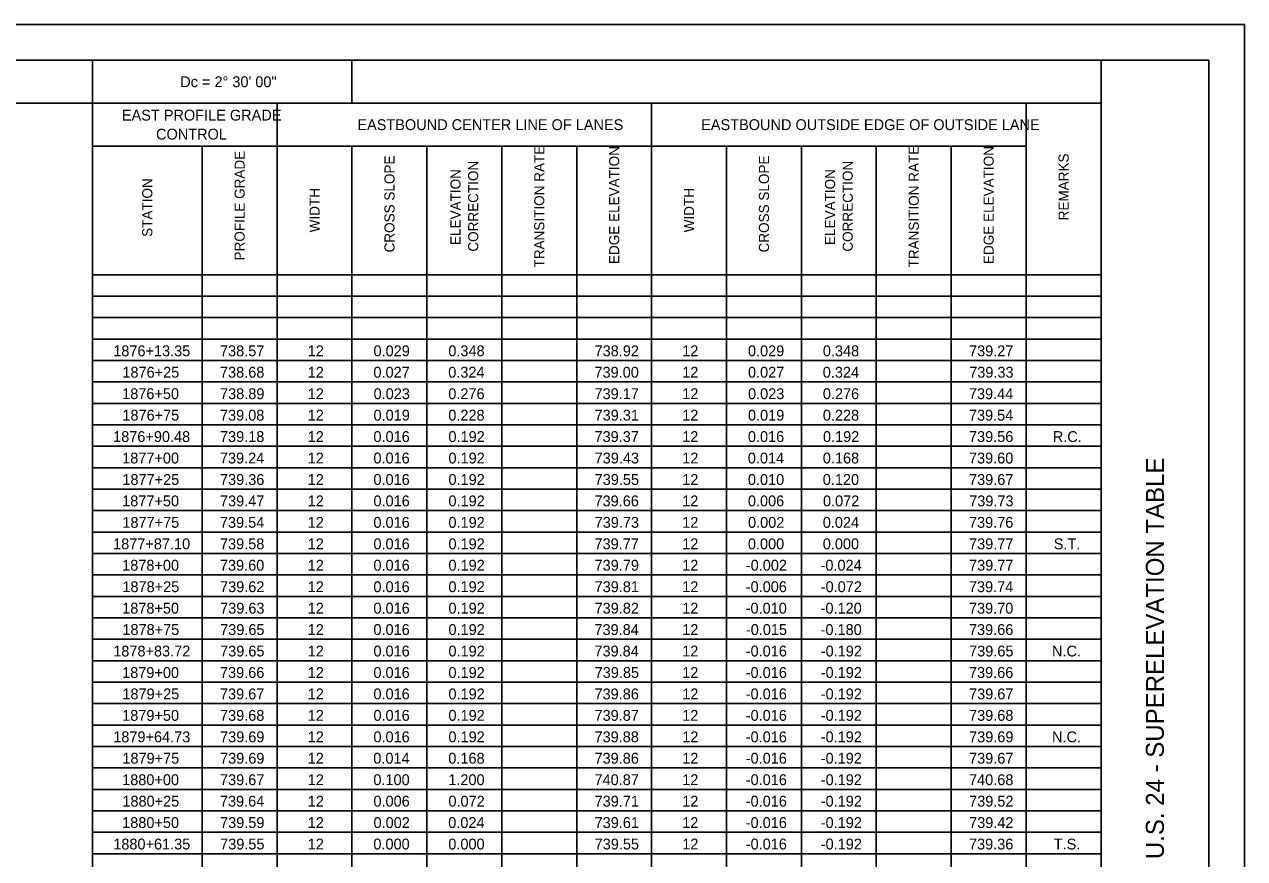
# Model space of a CAD drawing. Extents: x -174 to 34, y 0 to 22.
# Drawn here: x 17 to 34, y 10.38 to 22 of the extents above; entities that cross this region are included whole.
import ezdxf

# ---------------------------------------------------------------- set-up
doc = ezdxf.new("R2010")
doc.units = 0
for name, color, linetype in [('Default', 7, 'Continuous'), ('SH_Border', 7, 'Continuous'), ('SH_Cut_Line', 7, 'Continuous'), ('SH_Data', 7, 'Continuous')]:
    doc.layers.add(name, color=color, linetype=linetype)

msp = doc.modelspace()

# ---------------------------------------------------------------- linework, layer by layer
at = {"layer": 'Default'}
for p, q in [((1.5, 21.5), (32, 21.5)), ((17.947, 21.5), (17.947, 2.37)), ((21.564, 21.5), (21.564, 20.903)), ((32, 21.5), (32, 2.37)), ((1.5, 20.903), (32, 20.903)), ((20.521, 20.903), (20.521, 18.513)), ((25.739, 20.903), (25.739, 18.513)), ((30.956, 20.903), (30.956, 18.513)), ((17.947, 20.305), (30.956, 20.305)), ((19.477, 20.305), (19.477, 18.513)), ((21.564, 20.305), (21.564, 18.513)), ((22.608, 20.305), (22.608, 18.513)), ((23.651, 20.305), (23.651, 18.513)), ((24.695, 20.305), (24.695, 18.513)), ((26.782, 20.305), (26.782, 18.513)), ((27.826, 20.305), (27.826, 18.513)), ((28.869, 20.305), (28.869, 18.513)), ((29.913, 20.305), (29.913, 18.513)), ((17.947, 18.513), (32, 18.513)), ((19.477, 18.513), (19.477, 2.37)), ((20.521, 18.513), (20.521, 2.37)), ((21.564, 18.513), (21.564, 2.37)), ((22.608, 18.513), (22.608, 2.37)), ((23.651, 18.513), (23.651, 2.37)), ((24.695, 18.513), (24.695, 2.37)), ((25.739, 18.513), (25.739, 2.37)), ((26.782, 18.513), (26.782, 2.37)), ((27.826, 18.513), (27.826, 2.37)), ((28.869, 18.513), (28.869, 2.37)), ((29.913, 18.513), (29.913, 2.37)), ((30.956, 18.513), (30.956, 2.37)), ((17.947, 18.215), (32, 18.215)), ((17.947, 17.916), (32, 17.916)), ((17.947, 17.617), (32, 17.617)), ((17.947, 17.319), (32, 17.319)), ((17.947, 17.02), (32, 17.02)), ((17.947, 16.721), (32, 16.721)), ((17.947, 16.423), (32, 16.423)), ((17.947, 16.124), (32, 16.124)), ((17.947, 15.825), (32, 15.825)), ((17.947, 15.527), (32, 15.527)), ((17.947, 15.228), (32, 15.228)), ((17.947, 14.929), (32, 14.929)), ((17.947, 14.631), (32, 14.631)), ((17.947, 14.332), (32, 14.332)), ((17.947, 14.033), (32, 14.033)), ((17.947, 13.735), (32, 13.735)), ((17.947, 13.436), (32, 13.436)), ((17.947, 13.137), (32, 13.137)), ((17.947, 12.839), (32, 12.839)), ((17.947, 12.54), (32, 12.54)), ((17.947, 12.241), (32, 12.241)), ((17.947, 11.943), (32, 11.943)), ((17.947, 11.644), (32, 11.644)), ((17.947, 11.345), (32, 11.345)), ((17.947, 11.047), (32, 11.047)), ((17.947, 10.748), (32, 10.748)), ((17.947, 10.449), (32, 10.449))]:
    msp.add_line(p, q, dxfattribs=at)
at = {"layer": 'SH_Border'}
msp.add_line((32, 0.5), (32, 21.5), dxfattribs=at)
msp.add_lwpolyline([(1.5, 21.5), (33.5, 21.5), (33.5, 0.5), (1.5, 0.5)], close=True, dxfattribs=at)
at = {"layer": 'SH_Cut_Line'}
msp.add_lwpolyline([(0, 0), (34, 0), (34, 22), (0, 22)], close=True, dxfattribs=at)

# ---------------------------------------------------------------- texts
at = {"layer": 'Default'}
for s, height, p in [('Dc = 2° 30\' 00"', 0.15112, (19.171, 21.126)), ('EAST PROFILE GRADE ', 0.15112, (18.358, 20.661)), ('EASTBOUND CENTER LINE OF LANES', 0.15112, (21.639, 20.528)), ('EASTBOUND OUTSIDE EDGE OF OUTSIDE LANE', 0.15112, (26.429, 20.528)), ('CONTROL', 0.1511, (18.834, 20.396)), ('1876+13.35', 0.1511, (18.238, 17.378)), ('738.57', 0.1511, (19.725, 17.378)), ('12', 0.1511, (20.947, 17.378)), ('0.029', 0.1511, (21.864, 17.378)), ('0.348', 0.1511, (22.906, 17.378)), ('738.92', 0.1511, (24.944, 17.378)), ('12', 0.1511, (26.165, 17.378)), ('0.029', 0.1511, (27.081, 17.378)), ('0.348', 0.1511, (28.124, 17.378)), ('739.27', 0.1511, (30.161, 17.378)), ('1876+25', 0.1511, (18.365, 17.08)), ('738.68', 0.1511, (19.725, 17.08)), ('12', 0.1511, (20.947, 17.08)), ('0.027', 0.1511, (21.863, 17.08)), ('0.324', 0.1511, (22.905, 17.08)), ('739.00', 0.1511, (24.942, 17.08)), ('12', 0.1511, (26.165, 17.08)), ('0.027', 0.1511, (27.081, 17.08)), ('0.324', 0.1511, (28.123, 17.08)), ('739.33', 0.1511, (30.163, 17.08)), ('1876+50', 0.1511, (18.362, 16.781)), ('738.89', 0.1511, (19.726, 16.781)), ('12', 0.1511, (20.947, 16.781)), ('0.023', 0.1511, (21.865, 16.781)), ('0.276', 0.1511, (22.906, 16.781)), ('739.17', 0.1511, (24.943, 16.781)), ('12', 0.1511, (26.165, 16.781)), ('0.023', 0.1511, (27.082, 16.781)), ('0.276', 0.1511, (28.124, 16.781)), ('739.44', 0.1511, (30.159, 16.781)), ('1876+75', 0.1511, (18.365, 16.482)), ('739.08', 0.1511, (19.725, 16.482)), ('12', 0.1511, (20.947, 16.482)), ('0.019', 0.1511, (21.864, 16.482)), ('0.228', 0.1511, (22.906, 16.482)), ('739.31', 0.1511, (24.944, 16.482)), ('12', 0.1511, (26.165, 16.482)), ('0.019', 0.1511, (27.081, 16.482)), ('0.228', 0.1511, (28.124, 16.482)), ('739.54', 0.1511, (30.159, 16.482)), ('1876+90.48', 0.1511, (18.236, 16.184)), ('739.18', 0.1511, (19.725, 16.184)), ('12', 0.1511, (20.947, 16.184)), ('0.016', 0.1511, (21.863, 16.184)), ('0.192', 0.1511, (22.908, 16.184)), ('739.37', 0.1511, (24.943, 16.184)), ('12', 0.1511, (26.165, 16.184)), ('0.016', 0.1511, (27.08, 16.184)), ('0.192', 0.1511, (28.126, 16.184)), ('739.56', 0.1511, (30.16, 16.184)), ('R.C.', 0.1511, (31.328, 16.184)), ('1877+00', 0.1511, (18.362, 15.885)), ('739.24', 0.1511, (19.724, 15.885)), ('12', 0.1511, (20.947, 15.885)), ('0.016', 0.1511, (21.863, 15.885)), ('0.192', 0.1511, (22.908, 15.885)), ('739.43', 0.1511, (24.945, 15.885)), ('12', 0.1511, (26.165, 15.885)), ('0.014', 0.1511, (27.079, 15.885)), ('0.168', 0.1511, (28.124, 15.885)), ('739.60', 0.1511, (30.16, 15.885)), ('1877+25', 0.1511, (18.365, 15.586)), ('739.36', 0.1511, (19.725, 15.586)), ('12', 0.1511, (20.947, 15.586)), ('0.016', 0.1511, (21.863, 15.586)), ('0.192', 0.1511, (22.908, 15.586)), ('739.55', 0.1511, (24.945, 15.586)), ('12', 0.1511, (26.165, 15.586)), ('0.010', 0.1511, (27.08, 15.586)), ('0.120', 0.1511, (28.123, 15.586)), ('739.67', 0.1511, (30.161, 15.586)), ('1877+50', 0.1511, (18.362, 15.288)), ('739.47', 0.1511, (19.725, 15.288)), ('12', 0.1511, (20.947, 15.288)), ('0.016', 0.1511, (21.863, 15.288)), ('0.192', 0.1511, (22.908, 15.288)), ('739.66', 0.1511, (24.943, 15.288)), ('12', 0.1511, (26.165, 15.288)), ('0.006', 0.1511, (27.08, 15.288)), ('0.072', 0.1511, (28.126, 15.288)), ('739.73', 0.1511, (30.163, 15.288)), ('1877+75', 0.1511, (18.365, 14.989)), ('739.54', 0.1511, (19.724, 14.989)), ('12', 0.1511, (20.947, 14.989)), ('0.016', 0.1511, (21.863, 14.989)), ('0.192', 0.1511, (22.908, 14.989)), ('739.73', 0.1511, (24.945, 14.989)), ('12', 0.1511, (26.165, 14.989)), ('0.002', 0.1511, (27.082, 14.989)), ('0.024', 0.1511, (28.123, 14.989)), ('739.76', 0.1511, (30.16, 14.989)), ('1877+87.10', 0.1511, (18.236, 14.69)), ('739.58', 0.1511, (19.725, 14.69)), ('12', 0.1511, (20.947, 14.69)), ('0.016', 0.1511, (21.863, 14.69)), ('0.192', 0.1511, (22.908, 14.69)), ('739.77', 0.1511, (24.943, 14.69)), ('12', 0.1511, (26.165, 14.69)), ('0.000', 0.1511, (27.08, 14.69)), ('0.000', 0.1511, (28.123, 14.69)), ('739.77', 0.1511, (30.161, 14.69)), ('S.T.', 0.1511, (31.341, 14.69)), ('1878+00', 0.1511, (18.362, 14.392)), ('739.60', 0.1511, (19.724, 14.392)), ('12', 0.1511, (20.947, 14.392)), ('0.016', 0.1511, (21.863, 14.392)), ('0.192', 0.1511, (22.908, 14.392)), ('739.79', 0.1511, (24.944, 14.392)), ('12', 0.1511, (26.165, 14.392)), ('-0.002', 0.1511, (27.051, 14.392)), ('-0.024', 0.1511, (28.092, 14.392)), ('739.77', 0.1511, (30.161, 14.392)), ('1878+25', 0.1511, (18.365, 14.093)), ('739.62', 0.1511, (19.726, 14.093)), ('12', 0.1511, (20.947, 14.093)), ('0.016', 0.1511, (21.863, 14.093)), ('0.192', 0.1511, (22.908, 14.093)), ('739.81', 0.1511, (24.944, 14.093)), ('12', 0.1511, (26.165, 14.093)), ('-0.006', 0.1511, (27.05, 14.093)), ('-0.072', 0.1511, (28.095, 14.093)), ('739.74', 0.1511, (30.159, 14.093)), ('1878+50', 0.1511, (18.362, 13.794)), ('739.63', 0.1511, (19.727, 13.794)), ('12', 0.1511, (20.947, 13.794)), ('0.016', 0.1511, (21.863, 13.794)), ('0.192', 0.1511, (22.908, 13.794)), ('739.82', 0.1511, (24.944, 13.794)), ('12', 0.1511, (26.165, 13.794)), ('-0.010', 0.1511, (27.049, 13.794)), ('-0.120', 0.1511, (28.093, 13.794)), ('739.70', 0.1511, (30.16, 13.794)), ('1878+75', 0.1511, (18.365, 13.496)), ('739.65', 0.1511, (19.727, 13.496)), ('12', 0.1511, (20.947, 13.496)), ('0.016', 0.1511, (21.863, 13.496)), ('0.192', 0.1511, (22.908, 13.496)), ('739.84', 0.1511, (24.942, 13.496)), ('12', 0.1511, (26.165, 13.496)), ('-0.015', 0.1511, (27.052, 13.496)), ('-0.180', 0.1511, (28.093, 13.496)), ('739.66', 0.1511, (30.16, 13.496)), ('1878+83.72', 0.1511, (18.238, 13.197)), ('739.65', 0.1511, (19.727, 13.197)), ('12', 0.1511, (20.947, 13.197)), ('0.016', 0.1511, (21.863, 13.197)), ('0.192', 0.1511, (22.908, 13.197)), ('739.84', 0.1511, (24.942, 13.197)), ('12', 0.1511, (26.165, 13.197)), ('-0.016', 0.1511, (27.05, 13.197)), ('-0.192', 0.1511, (28.095, 13.197)), ('739.65', 0.1511, (30.162, 13.197)), ('N.C.', 0.1511, (31.317, 13.197)), ('1879+00', 0.1511, (18.362, 12.898)), ('739.66', 0.1511, (19.725, 12.898)), ('12', 0.1511, (20.947, 12.898)), ('0.016', 0.1511, (21.863, 12.898)), ('0.192', 0.1511, (22.908, 12.898)), ('739.85', 0.1511, (24.945, 12.898)), ('12', 0.1511, (26.165, 12.898)), ('-0.016', 0.1511, (27.05, 12.898)), ('-0.192', 0.1511, (28.095, 12.898)), ('739.66', 0.1511, (30.16, 12.898)), ('1879+25', 0.1511, (18.365, 12.6)), ('739.67', 0.1511, (19.725, 12.6)), ('12', 0.1511, (20.947, 12.6)), ('0.016', 0.1511, (21.863, 12.6)), ('0.192', 0.1511, (22.908, 12.6)), ('739.86', 0.1511, (24.943, 12.6)), ('12', 0.1511, (26.165, 12.6)), ('-0.016', 0.1511, (27.05, 12.6)), ('-0.192', 0.1511, (28.095, 12.6)), ('739.67', 0.1511, (30.161, 12.6)), ('1879+50', 0.1511, (18.362, 12.301)), ('739.68', 0.1511, (19.725, 12.301)), ('12', 0.1511, (20.947, 12.301)), ('0.016', 0.1511, (21.863, 12.301)), ('0.192', 0.1511, (22.908, 12.301)), ('739.87', 0.1511, (24.943, 12.301)), ('12', 0.1511, (26.165, 12.301)), ('-0.016', 0.1511, (27.05, 12.301)), ('-0.192', 0.1511, (28.095, 12.301)), ('739.68', 0.1511, (30.161, 12.301)), ('1879+64.73', 0.1511, (18.238, 12.002)), ('739.69', 0.1511, (19.726, 12.002)), ('12', 0.1511, (20.947, 12.002)), ('0.016', 0.1511, (21.863, 12.002)), ('0.192', 0.1511, (22.908, 12.002)), ('739.88', 0.1511, (24.943, 12.002)), ('12', 0.1511, (26.165, 12.002)), ('-0.016', 0.1511, (27.05, 12.002)), ('-0.192', 0.1511, (28.095, 12.002)), ('739.69', 0.1511, (30.162, 12.002)), ('N.C.', 0.1511, (31.317, 12.002)), ('1879+75', 0.1511, (18.365, 11.704)), ('739.69', 0.1511, (19.726, 11.704)), ('12', 0.1511, (20.947, 11.704)), ('0.014', 0.1511, (21.861, 11.704)), ('0.168', 0.1511, (22.906, 11.704)), ('739.86', 0.1511, (24.943, 11.704)), ('12', 0.1511, (26.165, 11.704)), ('-0.016', 0.1511, (27.05, 11.704)), ('-0.192', 0.1511, (28.095, 11.704)), ('739.67', 0.1511, (30.161, 11.704)), ('1880+00', 0.1511, (18.362, 11.405)), ('739.67', 0.1511, (19.725, 11.405)), ('12', 0.1511, (20.947, 11.405)), ('0.100', 0.1511, (21.862, 11.405)), ('1.200', 0.1511, (22.906, 11.405)), ('740.87', 0.1511, (24.943, 11.405)), ('12', 0.1511, (26.165, 11.405)), ('-0.016', 0.1511, (27.05, 11.405)), ('-0.192', 0.1511, (28.095, 11.405)), ('740.68', 0.1511, (30.161, 11.405)), ('1880+25', 0.1511, (18.365, 11.106)), ('739.64', 0.1511, (19.724, 11.106)), ('12', 0.1511, (20.947, 11.106)), ('0.006', 0.1511, (21.863, 11.106)), ('0.072', 0.1511, (22.908, 11.106)), ('739.71', 0.1511, (24.944, 11.106)), ('12', 0.1511, (26.165, 11.106)), ('-0.016', 0.1511, (27.05, 11.106)), ('-0.192', 0.1511, (28.095, 11.106)), ('739.52', 0.1511, (30.162, 11.106)), ('1880+50', 0.1511, (18.362, 10.808)), ('739.59', 0.1511, (19.726, 10.808)), ('12', 0.1511, (20.947, 10.808)), ('0.002', 0.1511, (21.864, 10.808)), ('0.024', 0.1511, (22.905, 10.808)), ('739.61', 0.1511, (24.944, 10.808)), ('12', 0.1511, (26.165, 10.808)), ('-0.016', 0.1511, (27.05, 10.808)), ('-0.192', 0.1511, (28.095, 10.808)), ('739.42', 0.1511, (30.162, 10.808)), ('1880+61.35', 0.1511, (18.238, 10.509)), ('739.55', 0.1511, (19.727, 10.509)), ('12', 0.1511, (20.947, 10.509)), ('0.000', 0.1511, (21.862, 10.509)), ('0.000', 0.1511, (22.906, 10.509)), ('739.55', 0.1511, (24.945, 10.509)), ('12', 0.1511, (26.165, 10.509)), ('-0.016', 0.1511, (27.05, 10.509)), ('-0.192', 0.1511, (28.095, 10.509)), ('739.36', 0.1511, (30.16, 10.509)), ('T.S.', 0.1511, (31.341, 10.509))]:
    msp.add_text(s, height=height, dxfattribs=at).set_placement(p)
for s, height, p in [('PROFILE GRADE', 0.14081, (20.069, 18.712)), ('TRANSITION RATE', 0.14081, (24.244, 18.615)), ('EDGE ELEVATION', 0.14081, (25.287, 18.663)), ('TRANSITION RATE', 0.14081, (29.461, 18.615)), ('EDGE ELEVATION', 0.14081, (30.505, 18.663)), ('CROSS SLOPE', 0.14081, (22.157, 18.824)), ('CORRECTION', 0.1408, (23.323, 18.835)), ('CROSS SLOPE', 0.14081, (27.374, 18.824)), ('CORRECTION', 0.1408, (28.541, 18.835)), ('REMARKS', 0.1408, (31.549, 19.271)), ('ELEVATION ', 0.1408, (23.077, 18.928)), ('ELEVATION ', 0.1408, (28.295, 18.928)), ('STATION', 0.1408, (18.782, 19.041)), ('WIDTH', 0.1408, (21.113, 19.104)), ('WIDTH', 0.1408, (26.331, 19.104))]:
    msp.add_text(s, height=height, rotation=90, dxfattribs=at).set_placement(p)
at = {"layer": 'SH_Data'}
msp.add_text('U.S. 24 - SUPERELEVATION TABLE', height=0.25, rotation=90, dxfattribs=at).set_placement((32.875, 10.375))

doc.saveas('drawing.dxf')
